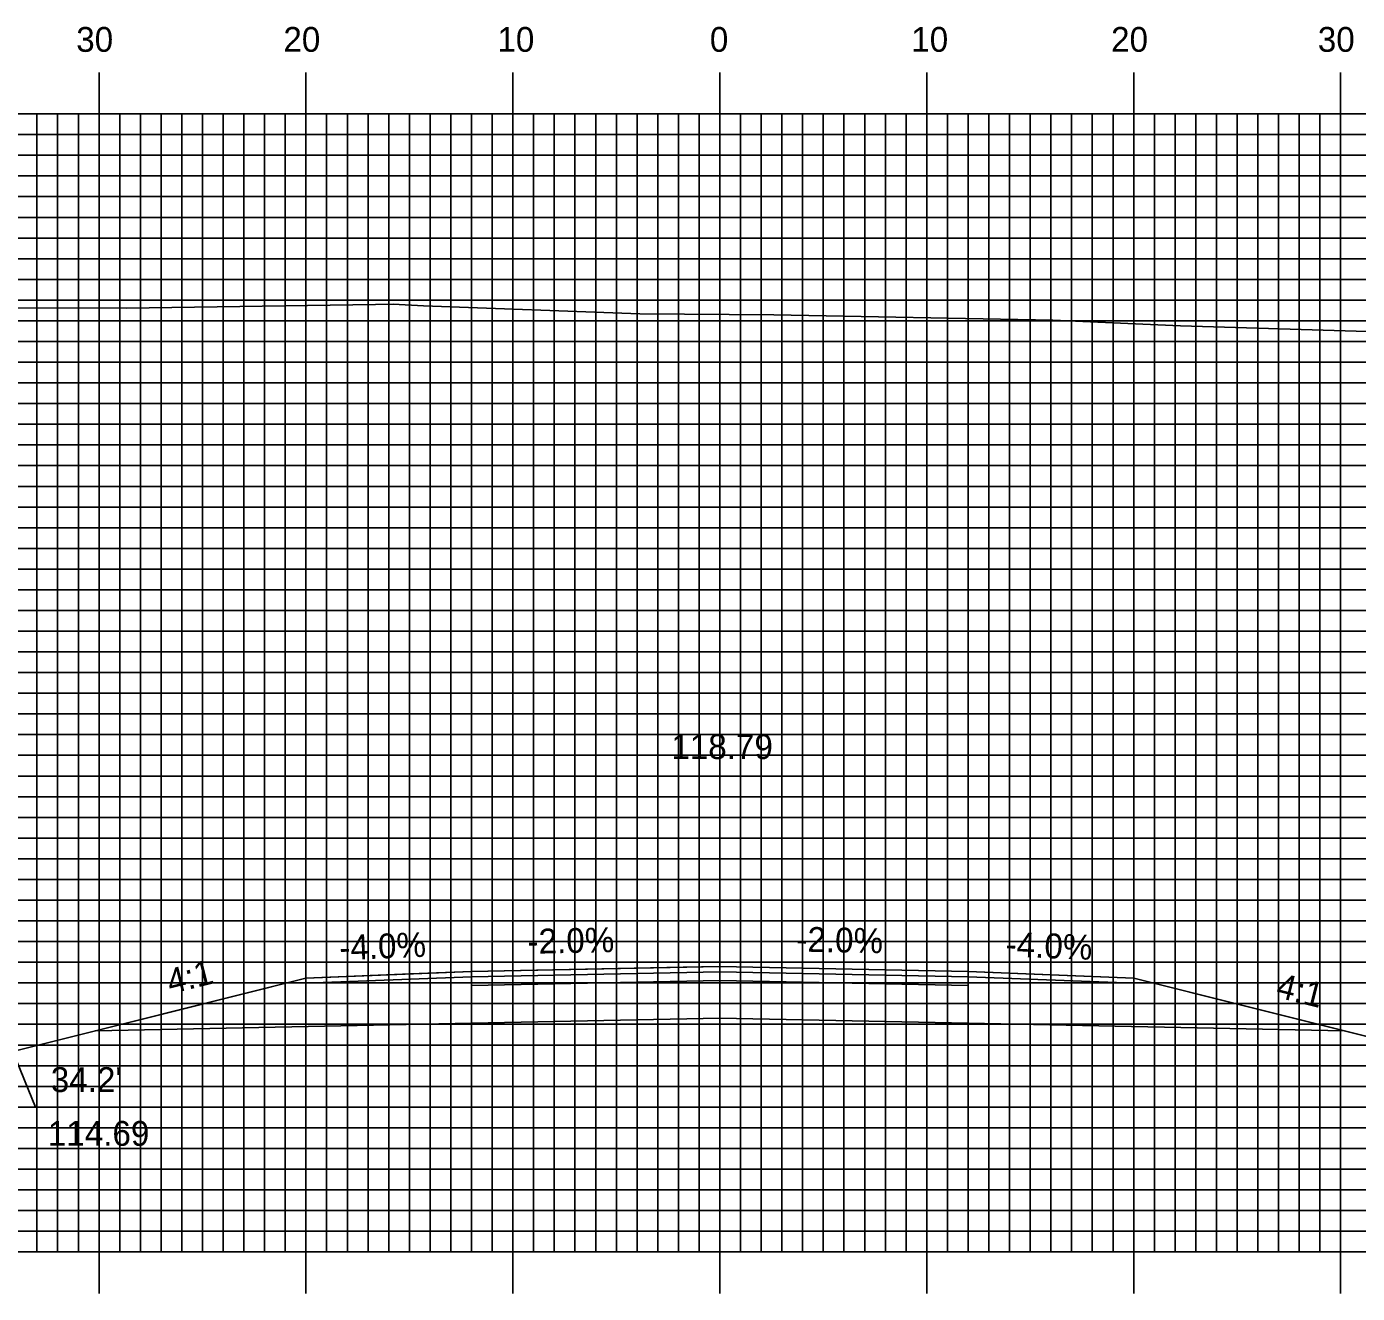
# Model space of a CAD drawing. Extents: x 1769661 to 1770005, y 442591 to 442811.
# Drawn here: x 1769793.5 to 1769857.8, y 442676.7 to 442737.9 of the extents above; entities that cross this region are included whole.
import ezdxf

# ---------------------------------------------------------------- set-up
doc = ezdxf.new("R2010")
doc.units = 0
for name, color, linetype in [('ANNOTATION', 7, 'Continuous'), ('D_Roadway_Centerline', 7, 'Continuous'), ('D_Roadway_Centerline_Text', 7, 'Continuous'), ('D_Roadway_Edge_Shoulder', 7, 'Continuous'), ('D_Roadway_Edge_TW', 7, 'Continuous'), ('D_Roadway_Pavement', 7, 'Continuous'), ('D_Roadway_SlopeLines', 7, 'Continuous'), ('D_Roadway_SubGrade', 7, 'Continuous'), ('H_V ANNOTATION', 7, 'Continuous'), ('MAJOR', 7, 'Continuous'), ('MINOR', 7, 'Continuous'), ('S_Roadway_Centerline', 7, 'Continuous')]:
    doc.layers.add(name, color=color, linetype=linetype)

msp = doc.modelspace()

# ---------------------------------------------------------------- linework, layer by layer
at = {"layer": 'ANNOTATION'}
msp.add_lwpolyline([(1769799.64, 442685.667), (1769793.948, 442685.667), (1769792.841, 442688.352)], dxfattribs=at)
at = {"layer": 'D_Roadway_Centerline'}
msp.add_lwpolyline([(1769792.841, 442688.352), (1769795.425, 442688.998), (1769796.841, 442689.352), (1769800.4, 442690.242), (1769807.015, 442691.896), (1769807.016, 442691.896), (1769812.064, 442692.098), (1769815.015, 442692.216), (1769825.239, 442692.421), (1769827.015, 442692.456), (1769839.015, 442692.216), (1769842.991, 442692.057), (1769847.015, 442691.896), (1769852.287, 442690.578), (1769857.189, 442689.352), (1769861.189, 442688.352)], dxfattribs=at)
at = {"layer": 'D_Roadway_Edge_Shoulder'}
for points in [[(1769815.015, 442692.216), (1769807.015, 442691.896), (1769807.015, 442691.646), (1769815.015, 442691.966)], [(1769839.015, 442692.216), (1769847.015, 442691.896), (1769847.015, 442691.646), (1769839.015, 442691.966)]]:
    msp.add_lwpolyline(points, close=True, dxfattribs=at)
at = {"layer": 'D_Roadway_Edge_TW'}
msp.add_lwpolyline([(1769815.015, 442691.966), (1769815.015, 442692.216), (1769827.015, 442692.456), (1769839.015, 442692.216), (1769839.015, 442691.966), (1769827.015, 442692.206)], close=True, dxfattribs=at)
at = {"layer": 'D_Roadway_Pavement'}
msp.add_lwpolyline([(1769815.015, 442691.549), (1769815.015, 442691.966), (1769827.015, 442692.206), (1769839.015, 442691.966), (1769839.015, 442691.549), (1769827.015, 442691.789)], close=True, dxfattribs=at)
at = {"layer": 'D_Roadway_SlopeLines'}
for points in [[(1769807.015, 442691.896), (1769792.841, 442688.352)], [(1769847.015, 442691.896), (1769861.189, 442688.352)]]:
    msp.add_lwpolyline(points, dxfattribs=at)
at = {"layer": 'D_Roadway_SubGrade'}
msp.add_lwpolyline([(1769815.015, 442689.716), (1769796.841, 442689.352), (1769807.015, 442691.896), (1769807.015, 442691.646), (1769815.015, 442691.966), (1769827.015, 442692.206), (1769839.015, 442691.966), (1769847.015, 442691.646), (1769847.015, 442691.896), (1769857.189, 442689.352), (1769839.015, 442689.716), (1769827.015, 442689.956)], close=True, dxfattribs=at)
at = {"layer": 'MAJOR'}
for p, q in [((1769797.015, 442735.669), (1769797.015, 442733.665)), ((1769807.015, 442735.669), (1769807.015, 442733.665)), ((1769817.015, 442735.669), (1769817.015, 442733.665)), ((1769827.015, 442735.669), (1769827.015, 442733.665)), ((1769837.015, 442735.669), (1769837.015, 442733.665)), ((1769847.015, 442735.669), (1769847.015, 442733.665)), ((1769857.015, 442735.669), (1769857.015, 442733.665)), ((1769687.015, 442733.665), (1769967.015, 442733.665)), ((1769687.015, 442733.665), (1769967.015, 442733.665)), ((1769797.015, 442678.665), (1769797.015, 442733.665)), ((1769807.015, 442678.665), (1769807.015, 442733.665)), ((1769817.015, 442678.665), (1769817.015, 442733.665)), ((1769827.015, 442678.665), (1769827.015, 442733.665)), ((1769837.015, 442678.665), (1769837.015, 442733.665)), ((1769847.015, 442678.665), (1769847.015, 442733.665)), ((1769857.015, 442678.665), (1769857.015, 442733.665)), ((1769687.015, 442728.665), (1769967.015, 442728.665)), ((1769687.015, 442723.665), (1769967.015, 442723.665)), ((1769687.015, 442718.665), (1769967.015, 442718.665)), ((1769687.015, 442713.665), (1769967.015, 442713.665)), ((1769687.015, 442708.665), (1769967.015, 442708.665)), ((1769687.015, 442703.665), (1769967.015, 442703.665)), ((1769687.015, 442698.665), (1769967.015, 442698.665)), ((1769687.015, 442693.665), (1769967.015, 442693.665)), ((1769687.015, 442688.665), (1769967.015, 442688.665)), ((1769687.015, 442683.665), (1769967.015, 442683.665)), ((1769687.015, 442678.665), (1769967.015, 442678.665)), ((1769687.015, 442678.665), (1769967.015, 442678.665)), ((1769797.015, 442676.661), (1769797.015, 442678.665)), ((1769807.015, 442676.661), (1769807.015, 442678.665)), ((1769817.015, 442676.661), (1769817.015, 442678.665)), ((1769827.015, 442676.661), (1769827.015, 442678.665)), ((1769837.015, 442676.661), (1769837.015, 442678.665)), ((1769847.015, 442676.661), (1769847.015, 442678.665)), ((1769857.015, 442676.661), (1769857.015, 442678.665))]:
    msp.add_line(p, q, dxfattribs=at)
at = {"layer": 'MINOR'}
for p, q in [((1769794.015, 442678.665), (1769794.015, 442733.665)), ((1769795.015, 442678.665), (1769795.015, 442733.665)), ((1769796.015, 442678.665), (1769796.015, 442733.665)), ((1769798.015, 442678.665), (1769798.015, 442733.665)), ((1769799.015, 442678.665), (1769799.015, 442733.665)), ((1769800.015, 442678.665), (1769800.015, 442733.665)), ((1769801.015, 442678.665), (1769801.015, 442733.665)), ((1769802.015, 442678.665), (1769802.015, 442733.665)), ((1769803.015, 442678.665), (1769803.015, 442733.665)), ((1769804.015, 442678.665), (1769804.015, 442733.665)), ((1769805.015, 442678.665), (1769805.015, 442733.665)), ((1769806.015, 442678.665), (1769806.015, 442733.665)), ((1769808.015, 442678.665), (1769808.015, 442733.665)), ((1769809.015, 442678.665), (1769809.015, 442733.665)), ((1769810.015, 442678.665), (1769810.015, 442733.665)), ((1769811.015, 442678.665), (1769811.015, 442733.665)), ((1769812.015, 442678.665), (1769812.015, 442733.665)), ((1769813.015, 442678.665), (1769813.015, 442733.665)), ((1769814.015, 442678.665), (1769814.015, 442733.665)), ((1769815.015, 442678.665), (1769815.015, 442733.665)), ((1769816.015, 442678.665), (1769816.015, 442733.665)), ((1769818.015, 442678.665), (1769818.015, 442733.665)), ((1769819.015, 442678.665), (1769819.015, 442733.665)), ((1769820.015, 442678.665), (1769820.015, 442733.665)), ((1769821.015, 442678.665), (1769821.015, 442733.665)), ((1769822.015, 442678.665), (1769822.015, 442733.665)), ((1769823.015, 442678.665), (1769823.015, 442733.665)), ((1769824.015, 442678.665), (1769824.015, 442733.665)), ((1769825.015, 442678.665), (1769825.015, 442733.665)), ((1769826.015, 442678.665), (1769826.015, 442733.665)), ((1769828.015, 442678.665), (1769828.015, 442733.665)), ((1769829.015, 442678.665), (1769829.015, 442733.665)), ((1769830.015, 442678.665), (1769830.015, 442733.665)), ((1769831.015, 442678.665), (1769831.015, 442733.665)), ((1769832.015, 442678.665), (1769832.015, 442733.665)), ((1769833.015, 442678.665), (1769833.015, 442733.665)), ((1769834.015, 442678.665), (1769834.015, 442733.665)), ((1769835.015, 442678.665), (1769835.015, 442733.665)), ((1769836.015, 442678.665), (1769836.015, 442733.665)), ((1769838.015, 442678.665), (1769838.015, 442733.665)), ((1769839.015, 442678.665), (1769839.015, 442733.665)), ((1769840.015, 442678.665), (1769840.015, 442733.665)), ((1769841.015, 442678.665), (1769841.015, 442733.665)), ((1769842.015, 442678.665), (1769842.015, 442733.665)), ((1769843.015, 442678.665), (1769843.015, 442733.665)), ((1769844.015, 442678.665), (1769844.015, 442733.665)), ((1769845.015, 442678.665), (1769845.015, 442733.665)), ((1769846.015, 442678.665), (1769846.015, 442733.665)), ((1769848.015, 442678.665), (1769848.015, 442733.665)), ((1769849.015, 442678.665), (1769849.015, 442733.665)), ((1769850.015, 442678.665), (1769850.015, 442733.665)), ((1769851.015, 442678.665), (1769851.015, 442733.665)), ((1769852.015, 442678.665), (1769852.015, 442733.665)), ((1769853.015, 442678.665), (1769853.015, 442733.665)), ((1769854.015, 442678.665), (1769854.015, 442733.665)), ((1769855.015, 442678.665), (1769855.015, 442733.665)), ((1769856.015, 442678.665), (1769856.015, 442733.665)), ((1769687.015, 442732.665), (1769967.015, 442732.665)), ((1769687.015, 442731.665), (1769967.015, 442731.665)), ((1769687.015, 442730.665), (1769967.015, 442730.665)), ((1769687.015, 442729.665), (1769967.015, 442729.665)), ((1769687.015, 442727.665), (1769967.015, 442727.665)), ((1769687.015, 442726.665), (1769967.015, 442726.665)), ((1769687.015, 442725.665), (1769967.015, 442725.665)), ((1769687.015, 442724.665), (1769967.015, 442724.665)), ((1769687.015, 442722.665), (1769967.015, 442722.665)), ((1769687.015, 442721.665), (1769967.015, 442721.665)), ((1769687.015, 442720.665), (1769967.015, 442720.665)), ((1769687.015, 442719.665), (1769967.015, 442719.665)), ((1769687.015, 442717.665), (1769967.015, 442717.665)), ((1769687.015, 442716.665), (1769967.015, 442716.665)), ((1769687.015, 442715.665), (1769967.015, 442715.665)), ((1769687.015, 442714.665), (1769967.015, 442714.665)), ((1769687.015, 442712.665), (1769967.015, 442712.665)), ((1769687.015, 442711.665), (1769967.015, 442711.665)), ((1769687.015, 442710.665), (1769967.015, 442710.665)), ((1769687.015, 442709.665), (1769967.015, 442709.665)), ((1769687.015, 442707.665), (1769967.015, 442707.665)), ((1769687.015, 442706.665), (1769967.015, 442706.665)), ((1769687.015, 442705.665), (1769967.015, 442705.665)), ((1769687.015, 442704.665), (1769967.015, 442704.665)), ((1769687.015, 442702.665), (1769967.015, 442702.665)), ((1769687.015, 442701.665), (1769967.015, 442701.665)), ((1769687.015, 442700.665), (1769967.015, 442700.665)), ((1769687.015, 442699.665), (1769967.015, 442699.665)), ((1769687.015, 442697.665), (1769967.015, 442697.665)), ((1769687.015, 442696.665), (1769967.015, 442696.665)), ((1769687.015, 442695.665), (1769967.015, 442695.665)), ((1769687.015, 442694.665), (1769967.015, 442694.665)), ((1769687.015, 442692.665), (1769967.015, 442692.665)), ((1769687.015, 442691.665), (1769967.015, 442691.665)), ((1769687.015, 442690.665), (1769967.015, 442690.665)), ((1769687.015, 442689.665), (1769967.015, 442689.665)), ((1769687.015, 442687.665), (1769967.015, 442687.665)), ((1769687.015, 442686.665), (1769967.015, 442686.665)), ((1769687.015, 442685.665), (1769967.015, 442685.665)), ((1769687.015, 442684.665), (1769967.015, 442684.665)), ((1769687.015, 442682.665), (1769967.015, 442682.665)), ((1769687.015, 442681.665), (1769967.015, 442681.665)), ((1769687.015, 442680.665), (1769967.015, 442680.665)), ((1769687.015, 442679.665), (1769967.015, 442679.665))]:
    msp.add_line(p, q, dxfattribs=at)
at = {"layer": 'S_Roadway_Centerline'}
msp.add_lwpolyline([(1769719.423, 442723.209), (1769733.43, 442723.28), (1769749.804, 442723.899), (1769751.318, 442723.929), (1769752.067, 442723.947), (1769755.626, 442723.897), (1769771.81, 442723.571), (1769775.271, 442723.69), (1769780.808, 442723.927), (1769791.114, 442724.294), (1769798.336, 442724.276), (1769810.379, 442724.461), (1769811.224, 442724.472), (1769812.696, 442724.389), (1769823.153, 442724.006), (1769829.621, 442723.96), (1769843.106, 442723.704), (1769849.283, 442723.426), (1769858.834, 442723.127)], dxfattribs=at)

# ---------------------------------------------------------------- texts
at = {"layer": 'ANNOTATION'}
for s, rotation, p in [('-4.0%', 2.29059, (1769808.647, 442692.763)), ('-2.0%', 1.14575, (1769817.733, 442693.071)), ('-2.0%', 358.85425, (1769830.701, 442693.183)), ('-4.0%', 357.7094, (1769840.807, 442692.946)), ('4:1', 14.03921, (1769800.464, 442691.12)), ('4:1', 345.9615, (1769853.836, 442690.993))]:
    msp.add_text(s, height=1.2, rotation=rotation, dxfattribs=at).set_placement(p)
for s, p in [("34.2'", (1769794.683, 442686.393)), ('114.69', (1769794.539, 442683.793))]:
    msp.add_text(s, height=1.2, dxfattribs=at).set_placement(p)
at = {"layer": 'D_Roadway_Centerline'}
for s, p in [('C', (1769827.01, 442692.456)), ('L', (1769827.015, 442692.449))]:
    msp.add_text(s, height=0.0146, dxfattribs=at).set_placement(p)
at = {"layer": 'D_Roadway_Centerline_Text'}
msp.add_text('118.79', height=1.2, dxfattribs=at).set_placement((1769824.671, 442702.486))
at = {"layer": 'H_V ANNOTATION'}
for s, p in [('30', (1769795.912, 442736.665)), ('20', (1769805.923, 442736.665)), ('10', (1769816.266, 442736.665)), ('0', (1769826.533, 442736.665)), ('10', (1769836.266, 442736.665)), ('20', (1769845.923, 442736.665)), ('30', (1769855.912, 442736.665))]:
    msp.add_text(s, height=1.2, dxfattribs=at).set_placement(p)

doc.saveas('drawing.dxf')
